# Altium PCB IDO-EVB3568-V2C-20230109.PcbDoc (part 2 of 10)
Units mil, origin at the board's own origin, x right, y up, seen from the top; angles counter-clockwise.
Board outline 5318 x 3544 mil, 2 copper layers (TOP, BOTTOM), stack 6.8 mil thick; 790 components, 626 nets, 2890 pads, 1922 vias.
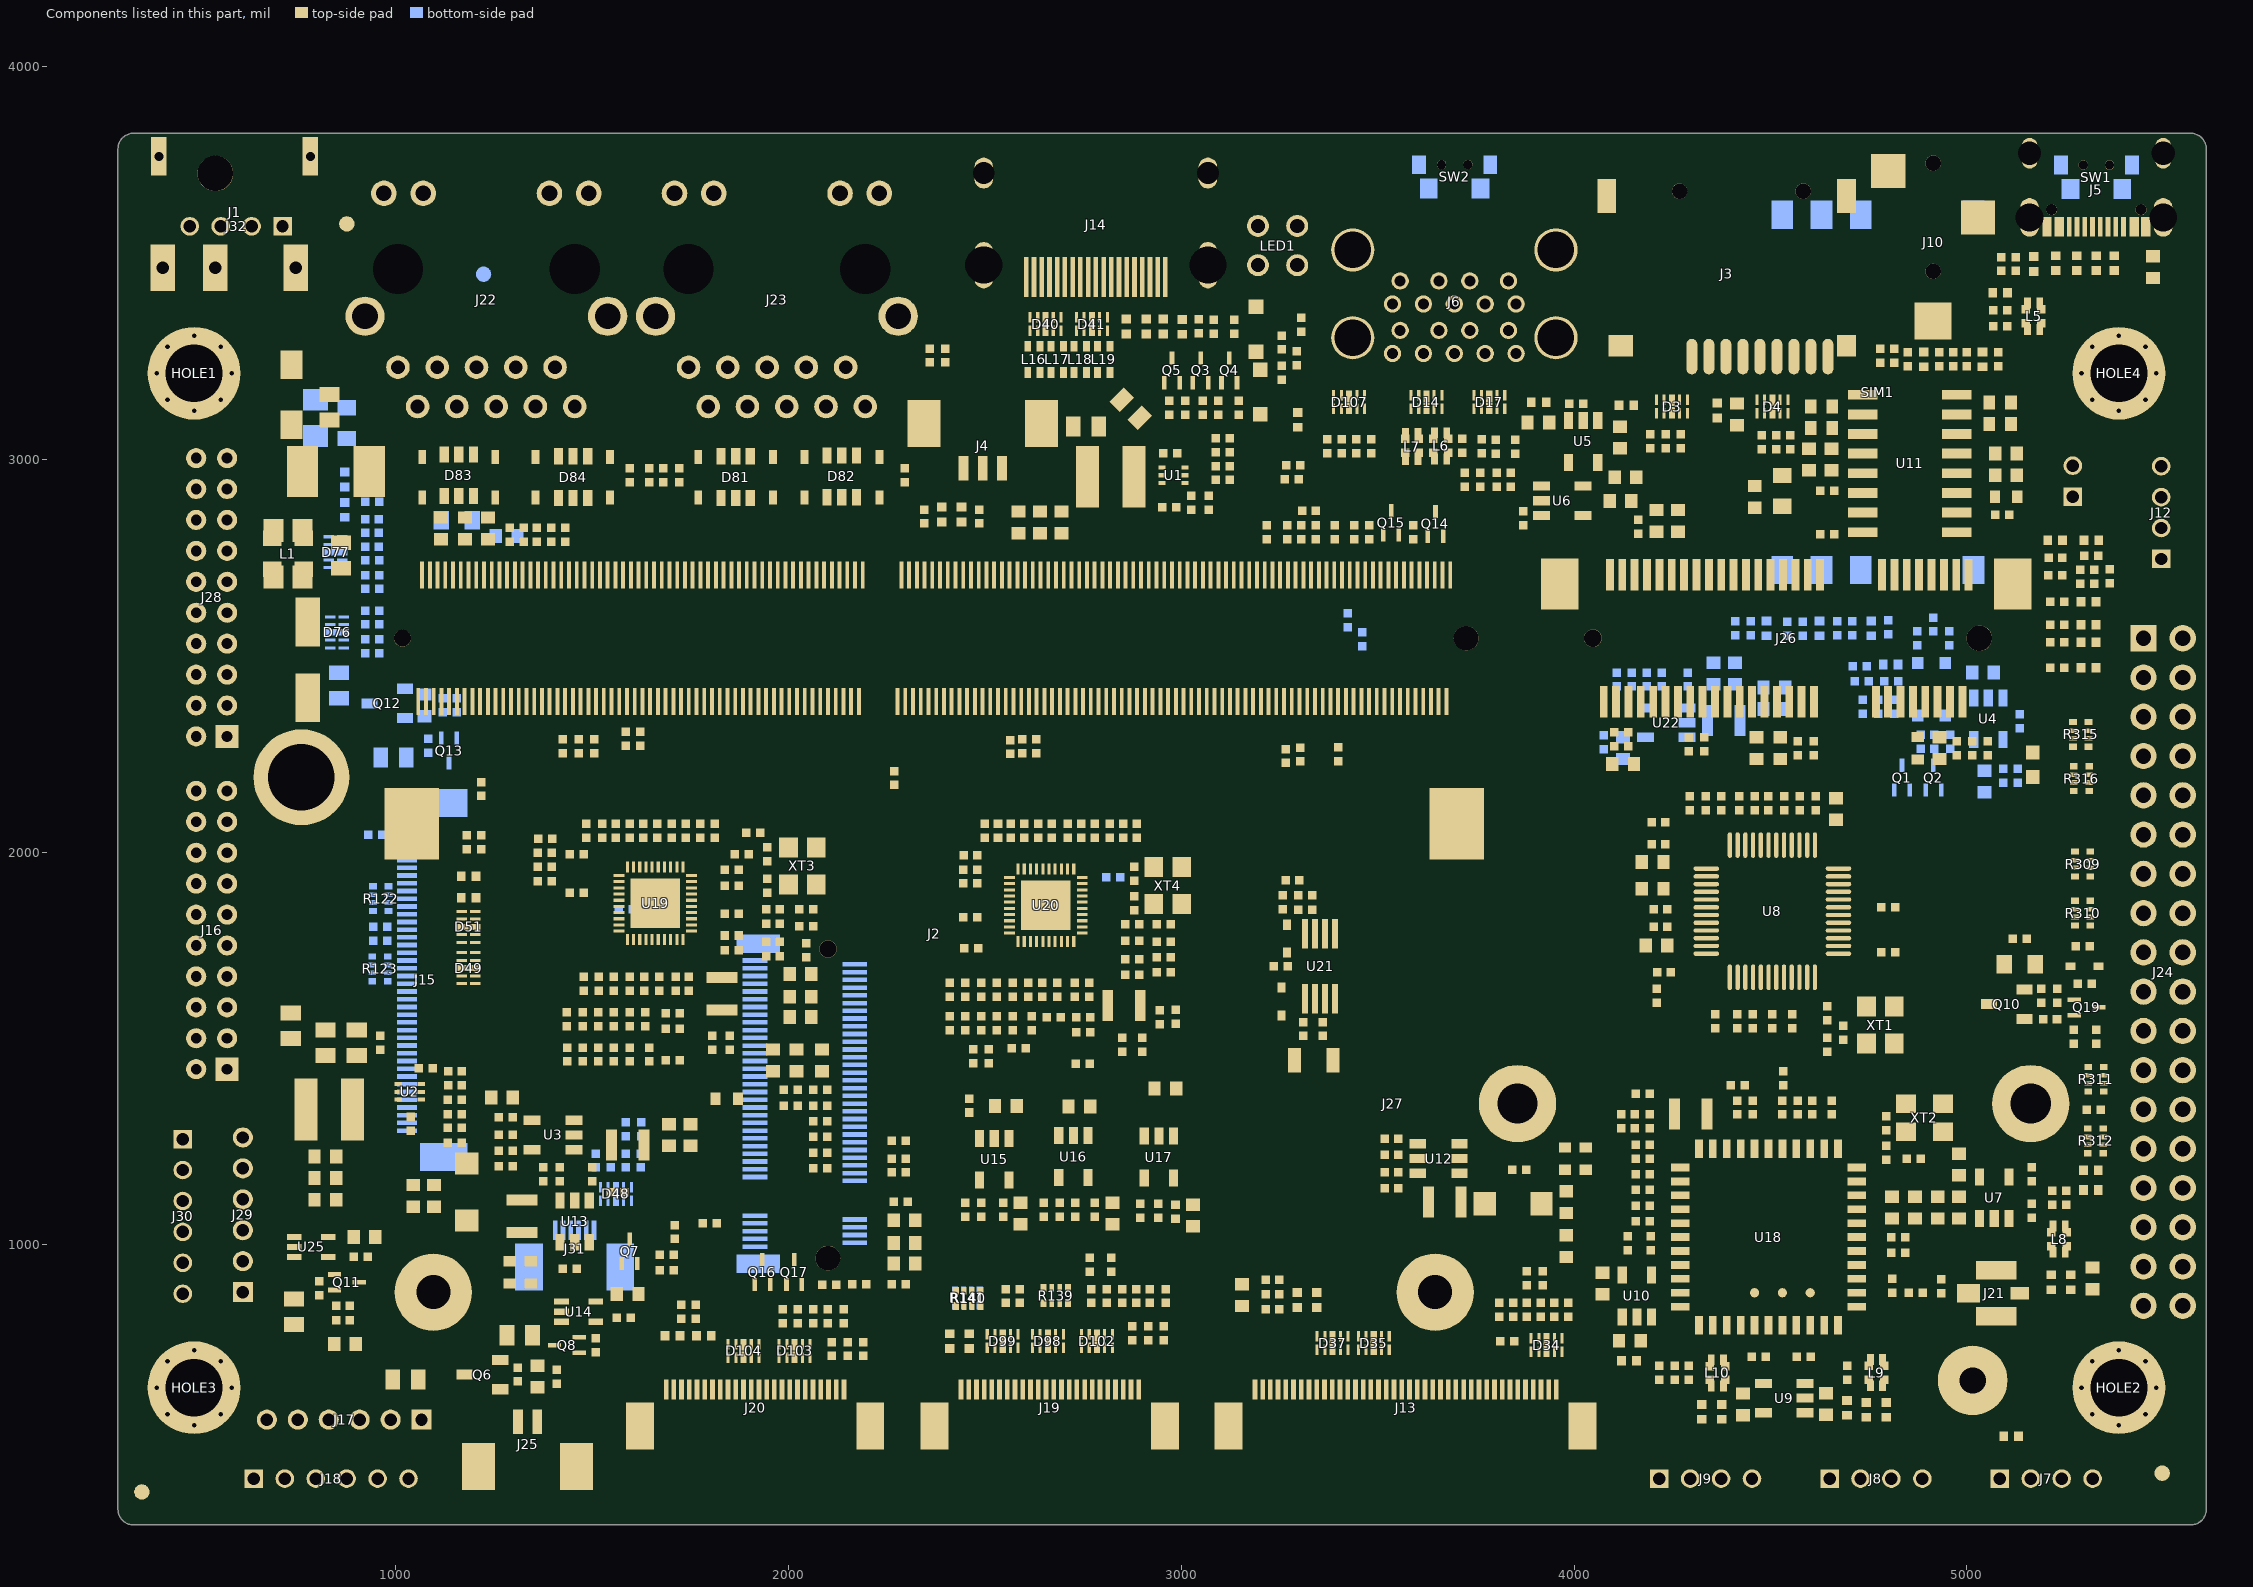
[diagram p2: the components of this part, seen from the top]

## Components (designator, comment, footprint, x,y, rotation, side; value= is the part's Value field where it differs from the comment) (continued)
R270 "R-0402_R0402_100R" SILKSCREEN_TOP#1 2875,1817 r180 top
R271 "R-0402_R0402_120R" SILKSCREEN_TOP#1 2955,1772 r180 top
R272 "R-0402_R0402_22R" SILKSCREEN_TOP#1 3269,2815 r90 top
R273 "R-0402_R0402_NC/4.7K" SILKSCREEN_TOP#1 2875,1688 r180 top
R274 "R-0402_R0402_4.7K" SILKSCREEN_TOP#1 2955,1695 r0 top
R275 "R-0402_R0402_22R" SILKSCREEN_TOP#1 3218,2815 r90 top
R276 "R-0402_R0402_22R" SILKSCREEN_TOP#1 3440,2815 r90 top
R277 "R-0402_R0402_NC/4.7K" SILKSCREEN_TOP#1 2875,1775 r180 top
R278 "R-0402_R0402_4.7K" SILKSCREEN_TOP#1 2955,1733 r0 top
R279 "R-0402_R0402_22R" SILKSCREEN_TOP#1 3390,2815 r90 top
R280 "R-0402_R0402_22R" SILKSCREEN_TOP#1 3400,2250 r270 top
R281 "R-0402_R0402_4.7K" SILKSCREEN_TOP#1 2875,1727 r180 top
R282 "R-0402_R0402_22R" SILKSCREEN_TOP#1 3342,2815 r90 top
R283 "R-0402_R0402_4.7K" SILKSCREEN_TOP#1 2410,1565 r270 top
R284 "R-0402_R0402_4.7K" SILKSCREEN_TOP#1 2646,1650 r90 top
R285 "R-0402_R0402_NC/4.7K" SILKSCREEN_TOP#1 2675,1580 r0 top
R286 "R-0402_R0402_4.7K" SILKSCREEN_TOP#1 2570,1650 r90 top
R287 "R-0402_R0402_4.7K" SILKSCREEN_TOP#1 2586,1501 r180 top
R288 "R-0402_R0402_NC/4.7K" SILKSCREEN_TOP#1 2530,1565 r270 top
R289 "R-0402_R0402_2.49K" SILKSCREEN_TOP#1 2886,2055 r270 top
R290 "R-0402_R0402_4.7K" SILKSCREEN_TOP#1 2490,1565 r90 top
R291 "R-0402_R0402_NC/4.7K" SILKSCREEN_TOP#1 2510,1480 r270 top
R293 "R-0402_R0402_NC/4.7K" SILKSCREEN_TOP#1 2450,1565 r90 top
R294 "R-0402_R0402_4.7K" SILKSCREEN_TOP#1 2470,1480 r270 top
R296 "R-0402_R0402_0R" SILKSCREEN_TOP#1 2462,1921 r0 top
R297 "R-0402_R0402_1.8K" SILKSCREEN_TOP#1 2462,1835 r180 top
R298 "R-0402_R0402_0R" SILKSCREEN_TOP#1 2749,1461 r180 top
R300 "R-0402_R0402_22R" SILKSCREEN_TOP#1 2530,1650 r270 top
R301 "R-0402_R0402_22R" SILKSCREEN_TOP#1 2490,1650 r270 top
R302 "R-0402_R0402_22R" SILKSCREEN_TOP#1 2450,1650 r270 top
R303 "R-0402_R0402_22R" SILKSCREEN_TOP#1 2410,1650 r270 top
R304 "R-0402_R0402_22R" SILKSCREEN_TOP#1 2610,1650 r270 top
R305 "R-0402_R0402_22R" SILKSCREEN_TOP#1 2570,1565 r270 top
R306 "R-0402_R0402_0R" SILKSCREEN_TOP#1 2986,1581 r90 top
R307 "R-0402_R0402_NC/2.2R" SILKSCREEN_TOP#1 5217,1120 r90 top
R308 "R-0402_R0402_NC/2.2R" SILKSCREEN_TOP#1 5253,1120 r90 top
R309 "RN_0402X4_RN_0402X4_22R" SILKSCREEN_TOP#28 5295,1970 r0 top
R310 "RN_0402X4_RN_0402X4_22R" SILKSCREEN_TOP#28 5295,1845 r0 top
R311 "RN_0402X4_RN_0402X4_22R" SILKSCREEN_TOP#28 5329,1422 r0 top
R312 "RN_0402X4_RN_0402X4_22R" SILKSCREEN_TOP#28 5328,1265 r0 top
R314 "R-0402_R0402_22R" SILKSCREEN_TOP#1 5323,1344 r0 top
R315 "RN_0402X4_RN_0402X4_22R" SILKSCREEN_TOP#28 5290,2300 r0 top
R316 "RN_0402X4_RN_0402X4_22R" SILKSCREEN_TOP#28 5292,2187.52 r0 top
R326 "R-0402_R0402_2.2K" SILKSCREEN_TOP#1 3283,1929 r180 top
R327 "R-0402_R0402_2.2K" SILKSCREEN_TOP#1 3258,1873 r90 top
R328 "R-0402_R0402_22R" SILKSCREEN_TOP#1 3315,1853 r180 top
R329 "R-0402_R0402_22R" SILKSCREEN_TOP#1 3315,1890 r180 top
R330 "R-0402_R0402_100R" ASSEMBLY_TOP#2 5085,3380 r0 top
R331 "R-0402_R0402_15K" ASSEMBLY_BOTTOM#3 4727,2474 r0 bottom
R332 "R-0402_R0402_10K" ASSEMBLY_BOTTOM#2 4543,2569 r270 bottom
R333 "R-0603_R0603_0R" ASSEMBLY_TOP#26 4875,2265 r270 top
R334 "R-0402_R0402_22R" ASSEMBLY_BOTTOM#3 4808,2436 r0 bottom
R335 "R-0402_R0402_22R" ASSEMBLY_BOTTOM#2 4800,2573 r270 bottom
R336 "R-0402_R0402_22R" ASSEMBLY_BOTTOM#2 4670,2570 r270 bottom
R337 "R-0402_R0402_22R" ASSEMBLY_TOP#2 4610,2265 r270 top
R340 "R-0402_R0402_0R" ASSEMBLY_TOP#2 4331,2275 r270 top
R341 "R-0402_R0402_0R" ASSEMBLY_TOP#2 4292,2275 r270 top
R342 "R-0402_R0402_1K" ASSEMBLY_TOP#2 5053,2265 r90 top
R343 "R-0402_R0402_53.6K" ASSEMBLY_BOTTOM#2 4185,2440 r90 bottom
R344 "R-0402_R0402_22R" ASSEMBLY_BOTTOM#2 4290,2440 r270 bottom
R345 "R-0402_R0402_10K" ASSEMBLY_BOTTOM#2 4109,2440 r270 bottom
R347 "R-0402_R0402_22R" SILKSCREEN_TOP#1 2280,1265 r180 top
R348 "R-0402_R0402_22R" SILKSCREEN_TOP#1 2280,1220 r180 top
R349 "R-0402_R0402_22R" SILKSCREEN_TOP#1 2280,1185 r180 top
R352 "R-0402_R0402_22R" SILKSCREEN_TOP#1 2285,1110 r180 top
R355 "R-0402_R0402_2.2R" SILKSCREEN_TOP#1 2080,1315 r180 top
R356 "R-0402_R0402_2.2R" SILKSCREEN_TOP#1 2080,1275 r180 top
R357 "R-0402_R0402_2.2R" SILKSCREEN_TOP#1 2005,1395 r180 top
R358 "R-0402_R0402_2.2R" SILKSCREEN_TOP#1 2005,1355 r180 top
R359 "R-0603_R0603_0R" SILKSCREEN_TOP#27 1842,1372 r0 top
R360 "R-0402_R0402_2.2R" SILKSCREEN_TOP#1 2080,1235 r180 top
R361 "R-0402_R0402_2.2R" SILKSCREEN_TOP#1 2080,1195 r180 top
R375 "R-0402_R0402_2.2R" SILKSCREEN_TOP#1 3715,3035 r90 top
R376 "R-0402_R0402_2.2R" SILKSCREEN_TOP#1 3765,3034 r90 top
R382 "R-0402_R0402_NC/22R" SILKSCREEN_TOP#1 1799,1055 r180 top
R384 "R-0402_R0402_NC/100K" SILKSCREEN_BOTTOM#3 940,2743 r0 bottom
R385 "R-0402_R0402_NC/100K" SILKSCREEN_BOTTOM#2 939,2848 r0 bottom
R387 "R-0402_R0402_NC/10K" SILKSCREEN_TOP#1 865,808 r0 top
R388 "R-0402_R0402_NC/10K" SILKSCREEN_TOP#1 805,890 r270 top
R389 "R-0402_R0402_0R" SILKSCREEN_TOP#1 865,845 r180 top
R390 "R-0402_R0402_0R" SILKSCREEN_TOP#1 910,970 r180 top
R391 "R-0402_R0402_100K" SILKSCREEN_BOTTOM#2 1119,2374 r270 bottom
R392 "R-0402_R0402_10K" SILKSCREEN_BOTTOM#2 1155,2374 r270 bottom
R393 "R-0402_R0402_1K" SILKSCREEN_BOTTOM#2 1082,2271 r270 bottom
R394 "R-0402_R0402_22R" SILKSCREEN_TOP#1 4825,980 r180 top
R398 "R-0402_R0402_10K" ASSEMBLY_TOP#2 5295,1760 r180 top
R399 "R-0402_R0402_10K" ASSEMBLY_TOP#2 5273,1530 r90 top
R400 "R-0402_R0402_10K" SILKSCREEN_TOP#1 5330,1530 r90 top
R401 "R-0402_R0402_10K" ASSEMBLY_TOP#2 5300,1665 r0 top
R408 "R-0402_R0402_NC/0R" SILKSCREEN_TOP#1 1168,1425 r90 top
R409 "R-0402_R0402_0R" SILKSCREEN_TOP#1 1133,1425 r90 top
R412 "R-0402_R0402_100R" SILKSCREEN_TOP#1 3285,2985 r0 top
R413 "R-0402_R0402_NC/0R" SILKSCREEN_TOP#1 3845,835 r270 top
R415 "R-0402_R0402_0R" SILKSCREEN_TOP#1 3810,835 r270 top
R416 "R-0402_R0402_22R" SILKSCREEN_TOP#1 2460,1355 r270 top
R417 "R-0402_R0402_22R" SILKSCREEN_TOP#1 1217,2025 r270 top
R418 "R-0402_R0402_22R" SILKSCREEN_TOP#1 3232,912 r0 top
R419 "R-0805_R0805_1M" SILKSCREEN_BOTTOM#15 875,3093 r90 bottom
R421 "R-0402_R0402_120R" SILKSCREEN_TOP#1 2595,2270 r270 top
R422 "R-0402_R0402_NC/0R" SILKSCREEN_TOP#1 3761,2949 r270 top
R423 "R-0402_R0402_NC/0R" SILKSCREEN_TOP#1 3722,2949 r270 top
R424 "R-0402_R0402_2.2R" SILKSCREEN_TOP#1 1595,2055 r90 top
R425 "R-0402_R0402_2.2R" SILKSCREEN_TOP#1 1630,2055 r90 top
SIM1 "J-SIM-021_0_SIM-91288-021_SIM" SILKSCREEN_BOTTOM#18 4613.43,3238.46 r270 bottom
SW1 "SW-TS24CA_PB-SIDE-S-3_5X4_5_T-S" SILKSCREEN_BOTTOM#19 5328.5,3720.5 r0 bottom
SW2 "SW-TS24CA_PB-SIDE-S-3_5X4_5_T-S" SILKSCREEN_BOTTOM#19 3694.5,3721.5 r0 bottom
U1 "U-ETA1654FSG_SOT563_ETA1654FSG" SILKSCREEN_TOP#29 2980,2960 r0 top
U2 "U-ETA1654FSG_SOT563_ETA1654FSG" SILKSCREEN_TOP#29 1035,1390 r0 top
U3 "U-ETA3417S2F_SOT23-5_ETA3417S2F" SILKSCREEN_TOP#30 1400,1280 r180 top
U4 "U-SY6280AAC_1_SOT23-5_SY6280AAC" SILKSCREEN_BOTTOM#20 5055,2340 r270 bottom
U5 "U-SY6280AAC_1_SOT23-5_SY6280AAC" SILKSCREEN_TOP#30 4023,3046 r270 top
U6 "U-SY6280AAC_1_SOT23-5_SY6280AAC" SILKSCREEN_TOP#30 3970,2895 r0 top
U7 "U-SY6280AAC_1_SOT23-5_SY6280AAC" SILKSCREEN_TOP#30 5070,1120 r90 top
U8 "U-FE2_0.1_LQFP-48_7X7X05P_FE1.1" ASSEMBLY_TOP#28 4505,1850 r90 top
U9 "U-SY6280AAC_1_SOT23-5_SY6280AAC" SILKSCREEN_TOP#30 4535,610 r180 top
U10 "U-SY6280AAC_1_SOT23-5_SY6280AAC" SILKSCREEN_TOP#30 4160,870 r90 top
U11 "U-NS4205_SOP16-P127-390X990_NS4" ASSEMBLY_TOP#29 4855,2990 r0 top
U12 "U-SY7201A_2_SOT23-6_SY7201ABC" SILKSCREEN_TOP#12 3655,1220 r180 top
U13 "U-SY7201A_2_SOT23-6_SY7201ABC" SILKSCREEN_TOP#12 1455,1060 r90 top
U14 "U-74LVC1G125GW-125_SOT353_NC/74" SILKSCREEN_TOP#31 1465,830 r0 top
U15 "U-ETA5050_SOT23-5_ETA5050V0S2F" SILKSCREEN_TOP#30 2523.57,1218.22 r270 top
U16 "U-ETA5050_SOT23-5_ETA5050V0S2F" SILKSCREEN_TOP#30 2725,1225 r270 top
U17 "U-ETA5050_SOT23-5_ETA5050V0S2F" SILKSCREEN_TOP#30 2942.72,1223.93 r270 top
U18 "MODULE_AP6XXX_WIFI_44P_12X12_AP" ASSEMBLY_TOP#30 4495,1020 r180 top
U19 "ETHERNET_RTL8211F_QFN-40_5X5X04" SILKSCREEN_TOP#32 1660,1870 r270 top
U20 "ETHERNET_RTL8211F_QFN-40_5X5X04" SILKSCREEN_TOP#32 2655,1865 r270 top
U21 "U-HYM8563S_TSSOP-8_HYM8563S" INFORMATION 3353,1710 r90 top
U22 "U-ETA3417_1_SOT23-5_ETA3417" SILKSCREEN_BOTTOM#21 4235,2330 r0 bottom
U25 "U-74LVC1G125GW-125_SOT353_NC/74" SILKSCREEN_TOP#31 783.84,995 r0 top
XT1 "XTAL-4P_XTAL_32X25_4P_IC_12MHZ" SILKSCREEN_TOP#33 4780,1560 r0 top
XT2 "XTAL-4P_XTAL_32X25_4P_IC_NC/26M" SILKSCREEN_TOP#33 4892,1324 r90 top
XT3 "XTAL-4P_XTAL_32X25_4P_IC_25MHZ" SILKSCREEN_TOP#33 2035,1965 r0 top
XT4 "XTAL-4P_XTAL_32X25_4P_IC_25MHZ" SILKSCREEN_TOP#33 2965,1915 r0 top
XT5 "XTAL-2P_XTAL_32X15_2P_IC_32.768" SILKSCREEN_TOP#34 3337,1470 r180 top

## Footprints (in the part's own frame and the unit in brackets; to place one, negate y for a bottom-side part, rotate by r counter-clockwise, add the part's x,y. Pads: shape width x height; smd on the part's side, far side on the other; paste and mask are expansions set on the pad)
ASSEMBLY_BOTTOM#1 [mm] "ASSEMBLY_BOTTOM"
  rect 0.8x0.9 smd: 1(-0.7,0) 2(0.7,0)
  silkscreen extent -1.35,-0.6 1.35,0.6, body extent -1.35,-0.6 1.35,0.6, height 3.81
ASSEMBLY_BOTTOM#2 [mm] "ASSEMBLY_BOTTOM"
  rect 0.55x0.55 smd: 1(-0.45,0) 2(0.45,0)
  TOP keep-out region: -0.127,-0.381 -0.127,0.381 0.127,0.381 0.127,-0.381
  silkscreen extent -0.9,-0.4 0.9,0.4, body extent -0.9,-0.4 0.9,0.4, height 3.81
ASSEMBLY_BOTTOM#3 [mm] "ASSEMBLY_BOTTOM"
  rect 0.55x0.55 smd: 1(0.45,0) 2(-0.45,0)
  TOP keep-out region: 0.127,0.381 0.127,-0.381 -0.127,-0.381 -0.127,0.381 0.127,0.381
  silkscreen extent -0.9,-0.4 0.9,0.4, body extent -0.9,-0.4 0.9,0.4, height 3.81
ASSEMBLY_BOTTOM#4 [mm] "ASSEMBLY_BOTTOM"
  rect 0.8x0.9 smd: 1(0.7,0) 2(-0.7,0)
  silkscreen extent -1.35,-0.6 1.35,0.6, body extent -1.35,-0.6 1.35,0.6, height 3.81
ASSEMBLY_BOTTOM#5 [mm] "ASSEMBLY_BOTTOM"
  round 6 / inner round 1.524 / far side round 6 hole 3.7: 1(0,0)
  round 0 / inner round 1.524 / far side round 0 hole 0.3: ""(-2.425,0)
  round 0.95 / inner round 1.524 / far side round 0.95 hole 0.3: ""(-1.715,-1.715) ""(-1.715,1.715) ""(0,-2.425) ""(0,2.425) ""(1.715,-1.715) ""(1.715,1.715) ""(2.425,0)
  body extent -3.01,-3.01 3.01,3.01, height 3.81
ASSEMBLY_BOTTOM#6 [mm] "ASSEMBLY_BOTTOM"
  rect 0.305x1.27 smd: 1(9.75,2.925) 2(9.25,2.925) 3(8.75,2.925) 4(8.25,2.925) 5(7.75,2.925) 6(7.25,2.925) 7(6.75,2.925) 8(6.25,2.925) 9(5.75,2.925) 10(5.25,2.925) 11(4.75,2.925) 12(4.25,2.925) 13(3.75,2.925) 14(3.25,2.925) 15(2.75,2.925) 16(2.25,2.925) 17(1.75,2.925) 18(1.25,2.925) 19(0.75,2.925) 20(0.25,2.925) 21(-0.25,2.925) 22(-0.75,2.925) 23(-1.25,2.925) 24(-1.75,2.925) 25(-2.25,2.925) 26(-2.75,2.925) 27(-3.25,2.925) 28(-3.75,2.925) 29(-4.25,2.925) 30(-4.75,2.925) 31(-5.25,2.925) 32(-5.75,2.925) 33(-6.25,2.925) 34(-6.75,2.925) 35(-7.25,2.925) 36(-7.75,2.925) 37(-8.25,2.925) 38(-8.75,2.925) 39(-9.25,2.925) 40(-9.75,2.925)
  rect 1.803x3.048 smd: 41(11.45,0.55) 42(-11.45,0.55)
  silkscreen extent -12.5,-3.65 12.5,3.54, body extent -12.5,-3.65 12.5,3.65, height 3.81
ASSEMBLY_BOTTOM#7 [mm] "ASSEMBLY_BOTTOM"
  rect 0.305x1.27 smd: 1(-1.25,-2.925) 2(-0.75,-2.925) 3(-0.25,-2.925) 4(0.25,-2.925) 5(0.75,-2.925) 6(1.25,-2.925)
  rect 1.803x3.048 smd: 7(-2.95,-0.55) 8(2.95,-0.55)
  silkscreen extent -4,-4.35 4,3.65, body extent -4,-3.65 4,3.65, height 3.81
ASSEMBLY_BOTTOM#8 [mm] "ASSEMBLY_BOTTOM"
  rect 0.7x2 smd: 1(-1.037,0) 2(1.063,0)
  TOP keep-out region: -0.597,-1.016 -0.597,1.016 0.622,1.016 0.622,-1.016 -0.597,-1.016
  silkscreen extent -1.51,-1.14 1.54,1.14, body extent -1.46,-1.04 1.46,1.04, height 3.81
ASSEMBLY_TOP#1 [mm] "ASSEMBLY_TOP"
  rect 0.8x0.9 smd: 1(-0.7,0) 2(0.7,0)
  silkscreen extent -1.35,-0.6 1.35,0.6, body extent -1.35,-0.6 1.35,0.6, height 3.81
ASSEMBLY_TOP#2 [mm] "ASSEMBLY_TOP"
  rect 0.55x0.55 smd: 1(-0.45,0) 2(0.45,0)
  TOP keep-out region: -0.127,-0.381 0.127,-0.381 0.127,0.381 -0.127,0.381 -0.127,-0.381
  silkscreen extent -0.9,-0.4 0.9,0.4, body extent -0.9,-0.4 0.9,0.4, height 3.81
ASSEMBLY_TOP#3 [mm] "ASSEMBLY_TOP"
  rect 0.2x0.68 smd: 1(-1,-0.437) 2(-0.5,-0.437) 4(0.5,-0.437) 5(1,-0.437) 6(1,0.437) 7(0.5,0.437) 9(-0.5,0.437) 10(-1,0.437)
  rect 0.4x0.75 smd: 3(0,-0.395) 8(0,0.395)
  silkscreen extent -1.43,-0.5 1.25,1.69
ASSEMBLY_TOP#4 [mm] "ASSEMBLY_TOP"
  rect 2.032x3.302 smd: 1(-2.159,0) 2(2.159,0)
  TOP keep-out region: -1.6,1.699 -1.6,-1.699 1.6,-1.699 1.6,1.699 -1.6,1.699
  silkscreen extent -3.5,-1.9 3.5,1.9, body extent -2.35,-1.7 2.35,1.7, height 3.81
ASSEMBLY_TOP#5 [mm] "ASSEMBLY_TOP"
  round 6.2 / inner round 1.524 / far side round 5 hole 4.3: 1(0,0)
  body extent -3.11,-3.11 3.11,3.11, height 3.81
ASSEMBLY_TOP#6 [mm] "ASSEMBLY_TOP"
  round 6 / inner round 1.524 / far side round 6 hole 3.7: 1(0,0)
  round 0.95 / inner round 1.524 / far side round 0.95 hole 0.3: ""(-2.425,0) ""(-1.715,-1.715) ""(-1.715,1.715) ""(0,-2.425) ""(0,2.425) ""(1.715,-1.715) ""(1.715,1.715)
  round 0 / inner round 1.524 / far side round 0 hole 0.3: ""(2.425,0)
  body extent -3.01,-3.01 3.01,3.01, height 3.81
ASSEMBLY_TOP#7 [mm] "ASSEMBLY_TOP"
  rect 1.2x1.2 / inner round 1.524 / far side rect 1.2x1.2 hole 0.8: 1(3,-0.45)
  round 1.2 / inner round 1.524 / far side round 1.2 hole 0.8: 2(1,-0.45) 3(-1,-0.45) 4(-3,-0.45)
  silkscreen extent -5,-2.25 5,2.25, body extent -5,-2.25 5,2.25, height 3.81
ASSEMBLY_TOP#8 [mm] "ASSEMBLY_TOP"
  rect 2.2x2.2 smd: 1(-3.2,-2.9) 2(-0.2,2.901)
  rect 2.4x2.4 smd: 3(6.5,0.001)
  round 1 / inner round 1.524 / far side round 1 hole 1: ""(-3.7,0.001) ""(3.3,0.001)
  silkscreen extent -7.7,-2.9 6.5,2.7, body extent -7.7,-4 7.7,4, height 3.81
ASSEMBLY_TOP#9 [mm] "ASSEMBLY_TOP"
  rect 1.2x1.2 / inner round 1.524 / far side rect 1.2x1.2 hole 0.8: 1(1,-0.45)
  round 1.2 / inner round 1.524 / far side round 1.2 hole 0.8: 2(-1,-0.45)
  silkscreen extent -3,-2.25 3,2.25, body extent -3,-2.25 3,2.25, height 3.81
ASSEMBLY_TOP#10 [mm] "ASSEMBLY_TOP"
  rect 0.305x1.27 smd: 1(9.75,2.925) 2(9.25,2.925) 3(8.75,2.925) 4(8.25,2.925) 5(7.75,2.925) 6(7.25,2.925) 7(6.75,2.925) 8(6.25,2.925) 9(5.75,2.925) 10(5.25,2.925) 11(4.75,2.925) 12(4.25,2.925) 13(3.75,2.925) 14(3.25,2.925) 15(2.75,2.925) 16(2.25,2.925) 17(1.75,2.925) 18(1.25,2.925) 19(0.75,2.925) 20(0.25,2.925) 21(-0.25,2.925) 22(-0.75,2.925) 23(-1.25,2.925) 24(-1.75,2.925) 25(-2.25,2.925) 26(-2.75,2.925) 27(-3.25,2.925) 28(-3.75,2.925) 29(-4.25,2.925) 30(-4.75,2.925) 31(-5.25,2.925) 32(-5.75,2.925) 33(-6.25,2.925) 34(-6.75,2.925) 35(-7.25,2.925) 36(-7.75,2.925) 37(-8.25,2.925) 38(-8.75,2.925) 39(-9.25,2.925) 40(-9.75,2.925)
  rect 1.803x3.048 smd: 41(11.45,0.55) 42(-11.45,0.55)
  silkscreen extent -12.5,-3.65 12.5,4.35, body extent -12.5,-3.65 12.5,3.65, height 3.81
ASSEMBLY_TOP#11 [mm] "ASSEMBLY_TOP"
  rect 0.3x2.6 smd: 1(-4.5,-4.95) 2(-4,-4.95) 3(-3.5,-4.95) 4(-3,-4.95) 5(-2.5,-4.95) 6(-2,-4.95) 7(-1.5,-4.95) 8(-1,-4.95) 9(-0.5,-4.95) 10(0,-4.95) 11(0.5,-4.95) 12(1,-4.95) 13(1.5,-4.95) 14(2,-4.95) 15(2.5,-4.95) 16(3,-4.95) 17(3.5,-4.95) 18(4,-4.95) 19(4.5,-4.95)
  oval 1.2x3 / inner round 1.524 / far side oval 1.2x3 hole 2.4 slot 0.7 at 0 deg: 20(7.25,-4.19) 21(-7.25,-4.19)
  oval 1.2x2 / inner round 1.524 / far side oval 1.2x2 hole 1.4 slot 0.7 at 0 deg: 22(-7.25,1.77) 23(7.25,1.77)
  silkscreen extent -7.5,-7.16 7.5,6.45, body extent -7.5,-6.45 7.5,6.45, height 3.81
ASSEMBLY_TOP#12 [mm] "ASSEMBLY_TOP"
  rect 1.5x1.5 / inner round 1.524 / far side rect 1.5x1.5 hole 0.7: 1(-9,-1)
  round 1.3 / inner round 1.524 / far side round 1.3 hole 0.7: 2(-9,1) 3(-7,-1) 4(-7,1) 5(-5,-1) 6(-5,1) 7(-3,-1) 8(-3,1) 9(-1,-1) 10(-1,1) 11(1,-1) 12(1,1) 13(3,-1) 14(3,1) 15(5,-1) 16(5,1) 17(7,-1) 18(7,1) 19(9,-1) 20(9,1)
  silkscreen extent -10,-3 10,8.15, body extent -10,-2 10,2, height 3.81
ASSEMBLY_TOP#13 [mm] "ASSEMBLY_TOP"
  rect 1.3x1.3 / inner round 1.524 / far side rect 1.3x1.3 hole 0.8: 1(-5,0)
  round 1.3 / inner round 1.524 / far side round 1.3 hole 0.8: 2(-3,0) 3(-1,0) 4(1,0) 5(3,0) 6(5,0)
  silkscreen extent -6.9,-1.73 6,1, body extent -6,-1 6,1, height 3.81
ASSEMBLY_TOP#14 [mm] "ASSEMBLY_TOP"
  rect 1.2x1.2 / inner round 1.524 / far side rect 1.2x1.2 hole 0.8: 1(5,-0.45)
  round 1.2 / inner round 1.524 / far side round 1.2 hole 0.8: 2(3,-0.45) 3(1,-0.45) 4(-1,-0.45) 5(-3,-0.45) 6(-5,-0.45)
  silkscreen extent -7,-2.25 7,2.25, body extent -7,-2.25 7,2.25, height 3.81
ASSEMBLY_TOP#15 [mm] "ASSEMBLY_TOP"
  rect 0.305x1.27 smd: 1(5.75,2.925) 2(5.25,2.925) 3(4.75,2.925) 4(4.25,2.925) 5(3.75,2.925) 6(3.25,2.925) 7(2.75,2.925) 8(2.25,2.925) 9(1.75,2.925) 10(1.25,2.925) 11(0.75,2.925) 12(0.25,2.925) 13(-0.25,2.925) 14(-0.75,2.925) 15(-1.25,2.925) 16(-1.75,2.925) 17(-2.25,2.925) 18(-2.75,2.925) 19(-3.25,2.925) 20(-3.75,2.925) 21(-4.25,2.925) 22(-4.75,2.925) 23(-5.25,2.925) 24(-5.75,2.925)
  rect 1.803x3.048 smd: 25(7.45,0.55) 26(-7.45,0.55)
  silkscreen extent -8.5,-3.65 8.5,4.35, body extent -8.5,-3.65 8.5,3.65, height 3.81
ASSEMBLY_TOP#16 [mm] "ASSEMBLY_TOP"
  rect 1.2x0.8 smd: 1(-1.737,0)
  rect 1.5x1.2 smd: 2(1.587,0)
  rect 2.65x1.2 smd: 3(-0.212,-1.5) 4(-0.212,1.5)
  TOP keep-out region: 1.312,0.9 -1.112,0.9 -1.112,-0.9 1.312,-0.9 1.312,0.9
  silkscreen extent -1.91,-1.62 1.75,1.62, body extent -2.34,-2.1 2.34,2.1, height 3.81
ASSEMBLY_TOP#17 [mm] "ASSEMBLY_TOP"
  round 1.524 hole 0.889: 1(5.715,-9.14) 2(4.445,-6.6) 3(3.175,-9.14) 4(1.905,-6.6) 5(0.635,-9.14) 6(-0.635,-6.6) 7(-1.905,-9.14) 8(-3.175,-6.6) 9(-4.445,-9.14) 10(-5.715,-6.6)
  round 1.651 / inner round 1.524 / far side round 1.651 hole 1.016: 11(6.624,4.65) 12(4.084,4.65) 13(-4.084,4.65) 14(-6.624,4.65)
  round 2.54 / inner round 1.524 / far side round 2.54 hole 1.651: SH1(-7.846,-3.301) SH2(7.846,-3.301)
  round 2.997 / inner round 1.524 / far side round 2.997 hole 3.251 unplated: ""(-5.715,-0.25) ""(5.715,-0.25)
  Multi-Layer keep-out region: -3.495,-0.249 -3.537,0.184 -3.664,0.6 -3.869,0.984 -4.145,1.321 -4.481,1.597 -4.865,1.802 -5.282,1.928 -5.715,1.971 -6.148,1.928 -6.565,1.802 -6.82,1.665 -6.82,1.665 -6.949,1.597 -7.285,1.321 -7.561,0.984 -7.766,0.6 -7.893,0.184 -7.935,-0.249 -7.893,-0.683 -7.766,-1.099 -7.561,-1.483 -7.285,-1.82 -6.949,-2.096 -6.82,-2.164 -6.82,-2.164 -6.565,-2.301 -6.148,-2.427 -5.715,-2.47 -5.282,-2.427 -4.865,-2.301 -4.481,-2.096 -4.145,-1.82 -3.869,-1.483 -3.664,-1.099 -3.537,-0.683 -3.495,-0.249
  Multi-Layer keep-out region: 7.935,-0.249 7.893,0.184 7.766,0.6 7.561,0.984 7.285,1.321 6.949,1.597 6.565,1.802 6.148,1.928 5.715,1.971 5.282,1.928 4.865,1.802 4.61,1.665 4.61,1.665 4.481,1.597 4.145,1.321 3.869,0.984 3.664,0.6 3.537,0.184 3.495,-0.249 3.537,-0.683 3.664,-1.099 3.869,-1.483 4.145,-1.82 4.481,-2.096 4.61,-2.164 4.61,-2.164 4.865,-2.301 5.282,-2.427 5.715,-2.47 6.148,-2.427 6.565,-2.301 6.949,-2.096 7.285,-1.82 7.561,-1.483 7.766,-1.099 7.893,-0.683 7.935,-0.249
  silkscreen extent -8.1,-10.65 8.1,10.65, body extent -8.1,-10.65 8.1,10.65, height 3.81
ASSEMBLY_TOP#18 [mm] "ASSEMBLY_TOP"
  rect 1.7x1.7 / inner round 1.524 / far side rect 1.7x1.7 hole 1: 1(-21.59,-1.27)
  round 1.7 / inner round 1.524 / far side round 1.7 hole 1: 2(-21.59,1.27) 3(-19.05,-1.27) 4(-19.05,1.27) 5(-16.51,-1.27) 6(-16.51,1.27) 7(-13.97,-1.27) 8(-13.97,1.27) 9(-11.43,-1.27) 10(-11.43,1.27) 11(-8.89,-1.27) 12(-8.89,1.27) 13(-6.35,-1.27) 14(-6.35,1.27) 15(-3.81,-1.27) 16(-3.81,1.27) 17(-1.27,-1.27) 18(-1.27,1.27) 19(1.27,-1.27) 20(1.27,1.27) 21(3.81,-1.27) 22(3.81,1.27) 23(6.35,-1.27) 24(6.35,1.27) 25(8.89,-1.27) 26(8.89,1.27) 27(11.43,-1.27) 28(11.43,1.27) 29(13.97,-1.27) 30(13.97,1.27) 31(16.51,-1.27) 32(16.51,1.27) 33(19.05,-1.27) 34(19.05,1.27) 35(21.59,-1.27) 36(21.59,1.27)
  silkscreen extent -22.86,-3.54 22.86,2.54, body extent -22.86,-2.54 22.86,2.54, height 3.81
ASSEMBLY_TOP#19 [mm] "ASSEMBLY_TOP"
  rect 1.2x1.2 / inner round 1.524 / far side rect 1.2x1.2 hole 0.8: 1(5,-2.45)
  round 1.2 / inner round 1.524 / far side round 1.2 hole 0.8: 2(3,-2.45) 3(1,-2.45) 4(-1,-2.45) 5(-3,-2.45) 6(-5,-2.45)
  silkscreen extent -7,-3.8 7,3.8, body extent -7,-3.8 7,3.8, height 3.81
ASSEMBLY_TOP#20 [mm] "ASSEMBLY_TOP"
  rect 1.5x1.3 smd: 1(-1.5,0.95) 2(-1.5,-0.95) 3(1.5,-0.95) 4(1.5,0.95)
  silkscreen extent -2.3,-1.7 2.3,1.7, body extent -2.3,-1.7 2.3,1.7, height 3.81
ASSEMBLY_TOP#21 [mm] "ASSEMBLY_TOP"
  rect 1.5x4 smd: 1(-1.5,0) 2(1.5,0)
  TOP keep-out region: -0.676,-2.013 0.683,-2.013 0.683,2.02 -0.676,2.02 -0.676,-2.013
  silkscreen extent -2.41,-2.16 2.41,2.16, body extent -2.29,-2.03 2.29,2.03, height 3.81
ASSEMBLY_TOP#22 [mm] "ASSEMBLY_TOP"
  rect 0.7x2 smd: 1(-1.037,0) 2(1.063,0)
  TOP keep-out region: -0.597,-1.016 0.622,-1.016 0.622,1.016 -0.597,1.016
  silkscreen extent -1.51,-1.14 1.54,1.14, body extent -1.46,-1.04 1.46,1.04, height 3.81
ASSEMBLY_TOP#23 [mm] "ASSEMBLY_TOP"
  round 1.422 / inner round 1.524 / far side round 1.422 hole 0.914: 1(-1.27,1.83) 2(1.27,1.83) 3(-1.27,4.37) 4(1.27,4.37)
  silkscreen extent -3.1,-5.75 2.15,5.75, body extent -2.15,-5.75 2.15,5.75, height 3.81
ASSEMBLY_TOP#24 [mm] "ASSEMBLY_TOP"
  rect 0.9x0.9 smd: 1(-0.8,0) 2(0.8,0)
  silkscreen extent -2.16,-0.65 1.4,0.65, body extent -1.25,-0.45 1.25,0.45, height 3.81
ASSEMBLY_TOP#25 [mm] "ASSEMBLY_TOP"
  round 1 smd: 1(0,0)
  TOP keep-out region: 1.261,0 1.218,0.326 1.092,0.63 0.892,0.892 0.63,1.092 0.326,1.218 0,1.261 -0.326,1.218 -0.63,1.092 -0.63,1.092 -0.892,0.892 -1.092,0.63 -1.218,0.326 -1.261,0 -1.218,-0.326 -1.092,-0.63 -0.892,-0.892 -0.63,-1.092 -0.63,-1.092 -0.326,-1.218 0,-1.261 0.326,-1.218 0.63,-1.092 0.892,-0.892 1.092,-0.63 1.218,-0.326 1.261,0
  TOP keep-out region: 1.261,0 1.218,0.326 1.092,0.63 0.892,0.892 0.63,1.092 0.326,1.218 0,1.261 -0.326,1.218 -0.63,1.092 -0.63,1.092 -0.892,0.892 -1.092,0.63 -1.218,0.326 -1.261,0 -1.218,-0.326 -1.092,-0.63 -0.892,-0.892 -0.63,-1.092 -0.63,-1.092 -0.326,-1.218 0,-1.261 0.326,-1.218 0.63,-1.092 0.892,-0.892 1.092,-0.63 1.218,-0.326 1.261,0
  body extent -1.26,-1.26 1.26,1.26, height 3.81
ASSEMBLY_TOP#26 [mm] "ASSEMBLY_TOP"
  rect 0.65x0.8 smd: 1(-0.725,0) 2(0.725,0)
  TOP keep-out region: -0.254,0.381 -0.254,-0.381 0.254,-0.381 0.254,0.381 -0.254,0.381
  silkscreen extent -1.35,-0.6 1.35,0.6, body extent -1.4,-0.64 1.4,0.64, height 3.81
ASSEMBLY_TOP#27 [mm] "ASSEMBLY_TOP"
  rect 1x1.2 smd: 1(-1,0) 2(1,0)
  TOP keep-out region: -0.381,0.635 -0.381,-0.635 0.381,-0.635 0.381,0.635 -0.381,0.635
  silkscreen extent -1.7,-0.95 1.7,0.95, body extent -1.78,-1.02 1.78,1.02, height 3.81
ASSEMBLY_TOP#28 [mm] "ASSEMBLY_TOP"
  oval 1.651x0.279 smd: 1(-4.275,2.751) 2(-4.275,2.25) 3(-4.275,1.75) 4(-4.275,1.25) 5(-4.275,0.749) 6(-4.275,0.249) 7(-4.275,-0.249) 8(-4.275,-0.749) 9(-4.275,-1.25) 10(-4.275,-1.75) 11(-4.275,-2.25) 12(-4.275,-2.751) 25(4.275,-2.751) 26(4.275,-2.25) 27(4.275,-1.75) 28(4.275,-1.25) 29(4.275,-0.749) 30(4.275,-0.249) 31(4.275,0.249) 32(4.275,0.749) 33(4.275,1.25) 34(4.275,1.75) 35(4.275,2.25) 36(4.275,2.751)
  oval 0.279x1.651 smd: 13(-2.751,-4.275) 14(-2.25,-4.275) 15(-1.75,-4.275) 16(-1.25,-4.275) 17(-0.749,-4.275) 18(-0.249,-4.275) 19(0.249,-4.275) 20(0.749,-4.275) 21(1.25,-4.275) 22(1.75,-4.275) 23(2.25,-4.275) 24(2.751,-4.275) 37(2.751,4.275) 38(2.25,4.275) 39(1.75,4.275) 40(1.25,4.275) 41(0.749,4.275) 42(0.249,4.275) 43(-0.249,4.275) 44(-0.749,4.275) 45(-1.25,4.275) 46(-1.75,4.275) 47(-2.25,4.275) 48(-2.751,4.275)
  silkscreen extent -6.5,-6.5 6.5,6.5, body extent -4.5,-4.5 4.5,4.5, height 3.81
ASSEMBLY_TOP#29 [mm] "ASSEMBLY_TOP"
  rect 1.905x0.635 smd: 1(-3.048,4.445) 2(-3.048,3.175) 3(-3.048,1.905) 4(-3.048,0.635) 5(-3.048,-0.635) 6(-3.048,-1.905) 7(-3.048,-3.175) 8(-3.048,-4.445) 9(3.048,-4.445) 10(3.048,-3.175) 11(3.048,-1.905) 12(3.048,-0.635) 13(3.048,0.635) 14(3.048,1.905) 15(3.048,3.175) 16(3.048,4.445)
  silkscreen extent -5.09,-4.95 1.91,4.95
ASSEMBLY_TOP#30 [mm] "ASSEMBLY_TOP"
  rect 1.2x0.5 smd: 1(-5.7,4.5) 2(-5.7,3.6) 3(-5.7,2.7) 4(-5.7,1.8) 5(-5.7,0.9) 6(-5.7,0) 7(-5.7,-0.9) 8(-5.7,-1.8) 9(-5.7,-2.7) 10(-5.7,-3.6) 11(-5.7,-4.5) 23(5.7,-4.5) 24(5.7,-3.6) 25(5.7,-2.7) 26(5.7,-1.8) 27(5.7,-0.9) 28(5.7,0) 29(5.7,0.9) 30(5.7,1.8) 31(5.7,2.7) 32(5.7,3.6) 33(5.7,4.5)
  rect 0.5x1.2 smd: 12(-4.5,-5.7) 13(-3.6,-5.7) 14(-2.7,-5.7) 15(-1.8,-5.7) 16(-0.9,-5.7) 17(0,-5.7) 18(0.9,-5.7) 19(1.8,-5.7) 20(2.7,-5.7) 21(3.6,-5.7) 22(4.5,-5.7) 34(4.5,5.7) 35(3.6,5.7) 36(2.7,5.7) 37(1.8,5.7) 38(0.9,5.7) 39(0,5.7) 40(-0.9,5.7) 41(-1.8,5.7) 42(-2.7,5.7) 43(-3.6,5.7) 44(-4.5,5.7)
  round 0.6 smd: 45(-2.7,3.6) 46(-0.9,3.6) 47(0.9,3.6)
  silkscreen extent -7.17,-6 6,6, body extent -6.35,-6 6.35,6, height 3.81
INFORMATION [mil] "INFORMATION"
  rect 75x15 smd: 1(-82.68,38.39) 2(-82.68,12.8) 3(-82.68,-12.8) 4(-82.68,-38.39) 5(82.68,-38.39) 6(82.68,-12.8) 7(82.68,12.8) 8(82.68,38.39)
  silkscreen extent -59,-59 59,59, body extent -134,-75 134,75, height 150
PLACE_BOUND_BOTTOM [mm] "PLACE_BOUND_BOTTOM"
  round 1 smd: 1(0,0)
  TOP keep-out region: 1.261,0 1.218,-0.326 1.092,-0.63 0.892,-0.892 0.63,-1.092 0.326,-1.218 0,-1.261 -0.326,-1.218 -0.63,-1.092 -0.63,-1.092 -0.892,-0.892 -1.092,-0.63 -1.218,-0.326 -1.261,0 -1.218,0.326 -1.092,0.63 -0.892,0.892 -0.63,1.092 -0.63,1.092 -0.326,1.218 0,1.261 0.326,1.218 0.63,1.092 0.892,0.892 1.092,0.63 1.218,0.326 1.261,0
  TOP keep-out region: 1.261,0 1.218,-0.326 1.092,-0.63 0.892,-0.892 0.63,-1.092 0.326,-1.218 0,-1.261 -0.326,-1.218 -0.63,-1.092 -0.63,-1.092 -0.892,-0.892 -1.092,-0.63 -1.218,-0.326 -1.261,0 -1.218,0.326 -1.092,0.63 -0.892,0.892 -0.63,1.092 -0.63,1.092 -0.326,1.218 0,1.261 0.326,1.218 0.63,1.092 0.892,0.892 1.092,0.63 1.218,0.326 1.261,0
  body extent -1.26,-1.26 1.26,1.26, height 3.81
PLACE_BOUND_TOP [mm] "PLACE_BOUND_TOP"
  round 1 smd: 1(0,0)
  TOP keep-out region: 1.261,0 1.218,0.326 1.092,0.63 0.892,0.892 0.63,1.092 0.326,1.218 0,1.261 -0.326,1.218 -0.63,1.092 -0.63,1.092 -0.892,0.892 -1.092,0.63 -1.218,0.326 -1.261,0 -1.218,-0.326 -1.092,-0.63 -0.892,-0.892 -0.63,-1.092 -0.63,-1.092 -0.326,-1.218 0,-1.261 0.326,-1.218 0.63,-1.092 0.892,-0.892 1.092,-0.63 1.218,-0.326 1.261,0
  TOP keep-out region: 1.261,0 1.218,0.326 1.092,0.63 0.892,0.892 0.63,1.092 0.326,1.218 0,1.261 -0.326,1.218 -0.63,1.092 -0.63,1.092 -0.892,0.892 -1.092,0.63 -1.218,0.326 -1.261,0 -1.218,-0.326 -1.092,-0.63 -0.892,-0.892 -0.63,-1.092 -0.63,-1.092 -0.326,-1.218 0,-1.261 0.326,-1.218 0.63,-1.092 0.892,-0.892 1.092,-0.63 1.218,-0.326 1.261,0
  body extent -1.26,-1.26 1.26,1.26, height 3.81
SILKSCREEN_BOTTOM#1 [mm] "SILKSCREEN_BOTTOM"
  rect 0.8x0.9 smd: 1(0.7,0) 2(-0.7,0)
  silkscreen extent -1.35,-0.6 1.35,0.6, body extent -1.35,-0.6 1.35,0.6, height 3.81
SILKSCREEN_BOTTOM#2 [mm] "SILKSCREEN_BOTTOM"
  rect 0.55x0.55 smd: 1(-0.45,0) 2(0.45,0)
  TOP keep-out region: -0.127,-0.381 -0.127,0.381 0.127,0.381 0.127,-0.381
  silkscreen extent -0.9,-0.4 0.9,0.4, body extent -0.9,-0.4 0.9,0.4, height 3.81
SILKSCREEN_BOTTOM#3 [mm] "SILKSCREEN_BOTTOM"
  rect 0.55x0.55 smd: 1(0.45,0) 2(-0.45,0)
  TOP keep-out region: 0.127,0.381 0.127,-0.381 -0.127,-0.381 -0.127,0.381 0.127,0.381
  silkscreen extent -0.9,-0.4 0.9,0.4, body extent -0.9,-0.4 0.9,0.4, height 3.81
SILKSCREEN_BOTTOM#4 [mm] "SILKSCREEN_BOTTOM"
  rect 0.95x1.3 smd: 1(0.825,0) 2(-0.825,0)
  silkscreen extent -1.7,-0.95 1.7,0.95, body extent -1.7,-0.95 1.7,0.95, height 3.81
SILKSCREEN_BOTTOM#5 [mm] "SILKSCREEN_BOTTOM"
  rect 0.8x0.9 smd: 1(-0.7,0) 2(0.7,0)
  silkscreen extent -1.35,-0.6 1.35,0.6, body extent -1.35,-0.6 1.35,0.6, height 3.81
SILKSCREEN_BOTTOM#6 [mm] "SILKSCREEN_BOTTOM"
  rect 0.95x1.3 smd: 1(-0.825,0) 2(0.825,0)
  silkscreen extent -1.7,-0.95 1.7,0.95, body extent -1.7,-0.95 1.7,0.95, height 3.81
SILKSCREEN_BOTTOM#7 [mm] "SILKSCREEN_BOTTOM"
  rect 1.4x1.6 smd: 1(-1.168,0) 2(1.168,0)
  silkscreen extent -2.2,-1 2.2,1, body extent -2.2,-1 2.2,1, height 3.81
SILKSCREEN_BOTTOM#8 [mm] "SILKSCREEN_BOTTOM"
  rect 0.8x0.75 smd: A(1.7,0) C(-1.7,0)
  silkscreen extent -1.97,-0.8 1.35,1.02, body extent -2.2,-1 2.2,1, height 3.81
SILKSCREEN_BOTTOM#9 [mm] "SILKSCREEN_BOTTOM"
  rect 0.2x0.68 smd: 1(1,0.437) 2(0.5,0.437) 4(-0.5,0.437) 5(-1,0.437) 6(-1,-0.437) 7(-0.5,-0.437) 9(0.5,-0.437) 10(1,-0.437)
  rect 0.4x0.75 smd: 3(0,0.395) 8(0,-0.395)
  silkscreen extent -1.25,-1 1.94,0.5, body extent -1.39,-0.64 1.39,0.64, height 3.81
SILKSCREEN_BOTTOM#10 [mm] "SILKSCREEN_BOTTOM"
  rect 0.57x0.62 smd: 1(-0.48,0) 2(0.48,0)
  silkscreen extent -0.98,-0.52 1,0.52, body extent -0.92,-0.46 0.92,0.46, height 3.81
SILKSCREEN_BOTTOM#11 [mm] "SILKSCREEN_BOTTOM"
  rect 0.2x0.68 smd: 1(-1,-0.437) 2(-0.5,-0.437) 4(0.5,-0.437) 5(1,-0.437) 6(1,0.437) 7(0.5,0.437) 9(-0.5,0.437) 10(-1,0.437)
  rect 0.4x0.75 smd: 3(0,-0.395) 8(0,0.395)
  silkscreen extent -1.43,-0.5 1.25,1.69
SILKSCREEN_BOTTOM#12 [mm] "SILKSCREEN_BOTTOM"
  rect 1.6x0.3 smd: 1(-40.525,-9.25) 2(-34.075,-9) 3(-40.525,-8.75) 4(-34.075,-8.5) 5(-40.525,-8.25) 6(-34.075,-8) 7(-40.525,-7.75) 8(-34.075,-7.5) 9(-40.525,-7.25) 10(-34.075,-7) 11(-40.525,-6.75) 12(-34.075,-6.5) 13(-40.525,-6.25) 14(-34.075,-6) 15(-40.525,-5.75) 16(-34.075,-5.5) 17(-40.525,-5.25) 18(-34.075,-5) 19(-40.525,-4.75) 20(-34.075,-4.5) 21(-40.525,-4.25) 22(-34.075,-4) 23(-40.525,-3.75) 24(-34.075,-3.5) 25(-40.525,-3.25) 26(-34.075,-3) 27(-40.525,-2.75) 28(-34.075,-2.5) 29(-40.525,-2.25) 30(-34.075,-2) 31(-40.525,-1.75) 32(-34.075,-1.5) 33(-40.525,-1.25) 34(-34.075,-1) 35(-40.525,-0.75) 36(-34.075,-0.5) 37(-40.525,-0.25) 38(-34.075,0) 39(-40.525,0.25) 40(-34.075,0.5) 41(-40.525,0.75) 42(-34.075,1) 43(-40.525,1.25) 44(-34.075,1.5) 45(-40.525,1.75) 46(-34.075,2) 47(-40.525,2.25) 48(-34.075,2.5) 49(-40.525,2.75) 50(-34.075,3) 51(-40.525,3.25) 52(-34.075,3.5) 53(-40.525,3.75) 54(-34.075,4) 55(-40.525,4.25) 56(-34.075,4.5) 57(-40.525,4.75) 58(-34.075,5) 67(-40.525,7.25) 68(-34.075,7.5) 69(-40.525,7.75) 70(-34.075,8) 71(-40.525,8.25) 72(-34.075,8.5) 73(-40.525,8.75) 74(-34.075,9) 75(-40.525,9.25)
  round 1.6 / inner round 1.524 / far side round 1.6 hole 1.6 unplated: 76(-35.8,10)
  round 1.118 / inner round 1.524 / far side round 1.118 hole 1.118 unplated: 77(-35.8,-10)
  rect 2.8x1.2 smd: G1(-40.3,10.35) G2(-40.3,-10.35)
  round 4.5 / inner round 1.524 / far side round 5 hole 2.6: G3(42,0) G4(8.8,0)
  silkscreen extent -42,-11.2 42,11.2, body extent -42,-11.2 42,11.2, height 3.81
SILKSCREEN_BOTTOM#13 [mm] "SILKSCREEN_BOTTOM"
  rect 0.85x0.3 smd: 1(-0.8,0.5) 2(-0.8,-0.5) 3(0.8,0)
  silkscreen extent -1.07,-0.8 0,1.28, body extent -1.5,-1.1 1.5,1.1, height 3.81
SILKSCREEN_BOTTOM#14 [mm] "SILKSCREEN_BOTTOM"
  rect 1.05x0.65 smd: 1(1.15,-0.95) 2(1.15,0.95) 3(-1.15,0)
  silkscreen extent -0.3,-1.92 1.52,1.45, body extent -1.95,-1.75 1.95,1.75, height 3.81
SILKSCREEN_BOTTOM#15 [mm] "SILKSCREEN_BOTTOM"
  rect 1x1.2 smd: 1(-1,0) 2(1,0)
  TOP keep-out region: -0.381,0.635 -0.381,-0.635 0.381,-0.635 0.381,0.635 -0.381,0.635
  silkscreen extent -1.7,-0.95 1.7,0.95, body extent -1.78,-1.02 1.78,1.02, height 3.81
SILKSCREEN_BOTTOM#16 [mm] "SILKSCREEN_BOTTOM"
  rect 0.5x0.399 smd: 1(0.5,-0.8) 4(0.5,0.8) 5(-0.5,0.8) 8(-0.5,-0.8)
  rect 0.5x0.3 smd: 2(0.5,-0.25) 3(0.5,0.25) 6(-0.5,0.25) 7(-0.5,-0.25)
  silkscreen extent -0.98,-1.28 0.98,1.28, body extent -0.9,-1.2 0.9,1.2, height 3.81
SILKSCREEN_BOTTOM#17 [mm] "SILKSCREEN_BOTTOM"
  rect 0.5x0.399 smd: 1(-0.5,0.8) 4(-0.5,-0.8) 5(0.5,-0.8) 8(0.5,0.8)
  rect 0.5x0.3 smd: 2(-0.5,0.25) 3(-0.5,-0.25) 6(0.5,-0.25) 7(0.5,0.25)
  silkscreen extent -0.98,-1.28 0.98,1.28, body extent -0.9,-1.2 0.9,1.2, height 3.81
SILKSCREEN_BOTTOM#18 [mm] "SILKSCREEN_BOTTOM"
  rect 1.829x1.397 smd: C1(13.199,2.119) C2(13.199,-0.421) C3(13.199,-2.961) C5(-9.772,2.119) C6(-9.772,-0.421) C7(-9.772,-2.961) CD1(13.199,-10.251) CD2(-9.772,-10.251)
  silkscreen extent -16.98,-12.51 17.02,12.49, body extent -17.05,-12.5 17.05,12.5, height 3.81
SILKSCREEN_BOTTOM#19 [mm] "SILKSCREEN_BOTTOM"
  rect 0.9x1.2 smd: 1(2.339,-0.749) 2(-2.263,-0.749)
  rect 1.15x1.3 smd: 3(1.713,0.801) 4(-1.637,0.801)
  round 0.6 / inner round 1.524 / far side round 0.6 hole 0.6 unplated: ""(-0.813,-0.749) ""(0.889,-0.749)
  silkscreen extent -2.86,-2.65 2.94,1.55, body extent -2.86,-1.44 2.86,1.44, height 3.81
SILKSCREEN_BOTTOM#20 [mm] "SILKSCREEN_BOTTOM"
  rect 1.1x0.6 smd: 1(-1.35,0.95) 2(-1.35,0) 3(-1.35,-0.95) 4(1.35,-0.95) 5(1.35,0.95)
  silkscreen extent -1.77,-1.45 0.48,1.87, body extent -2.15,-1.8 2.15,1.8, height 3.81
SILKSCREEN_BOTTOM#21 [mm] "SILKSCREEN_BOTTOM"
  rect 1.1x0.6 smd: 1(1.35,-0.95) 2(1.35,0) 3(1.35,0.95) 4(-1.35,0.95) 5(-1.35,-0.95)
  silkscreen extent -0.48,-1.65 1.78,1.45, body extent -2.15,-1.8 2.15,1.8, height 3.81
SILKSCREEN_TOP#1 [mm] "SILKSCREEN_TOP"
  rect 0.55x0.55 smd: 1(-0.45,0) 2(0.45,0)
  TOP keep-out region: -0.127,-0.381 0.127,-0.381 0.127,0.381 -0.127,0.381
  silkscreen extent -0.9,-0.4 0.9,0.4, body extent -0.9,-0.4 0.9,0.4, height 3.81
SILKSCREEN_TOP#2 [mm] "SILKSCREEN_TOP"
  rect 0.95x1.3 smd: 1(-0.825,0) 2(0.825,0)
  silkscreen extent -1.7,-0.95 1.7,0.95, body extent -1.7,-0.95 1.7,0.95, height 3.81
SILKSCREEN_TOP#3 [mm] "SILKSCREEN_TOP"
  rect 3.15x1.6 smd: 1(-2.45,0) 2(2.45,0)
  silkscreen extent -3.92,-3.3 3.3,3.3, body extent -4.55,-3.9 4.55,3.9, height 3.81
SILKSCREEN_TOP#4 [mm] "SILKSCREEN_TOP"
  rect 0.8x0.9 smd: 1(-0.7,0) 2(0.7,0)
  silkscreen extent -1.35,-0.6 1.35,0.6, body extent -1.35,-0.6 1.35,0.6, height 3.81
SILKSCREEN_TOP#5 [mm] "SILKSCREEN_TOP"
  rect 1.85x1.45 smd: A(1.95,0) C(-1.95,0)
  silkscreen extent -3.52,-1.35 2.5,1.35, body extent -3,-1.55 3,1.55, height 3.81
SILKSCREEN_TOP#6 [mm] "SILKSCREEN_TOP"
  rect 0.57x0.62 smd: 1(-0.48,0) 2(0.48,0)
  silkscreen extent -0.98,-0.52 1,0.52, body extent -0.92,-0.46 0.92,0.46, height 3.81
SILKSCREEN_TOP#7 [mm] "SILKSCREEN_TOP"
  rect 0.2x0.68 smd: 1(-1,-0.437) 2(-0.5,-0.437) 4(0.5,-0.437) 5(1,-0.437) 6(1,0.437) 7(0.5,0.437) 9(-0.5,0.437) 10(-1,0.437)
  rect 0.4x0.75 smd: 3(0,-0.395) 8(0,0.395)
  silkscreen extent -1.43,-0.5 1.25,1.69
SILKSCREEN_TOP#8 [mm] "SILKSCREEN_TOP"
  rect 1.43x1.53 smd: A(-1.84,0) C(1.84,0)
  silkscreen extent -1.75,-1.3 2.42,1.39, body extent -2.66,-1.45 2.66,1.45, height 3.81
SILKSCREEN_TOP#9 [mm] "SILKSCREEN_TOP"
  rect 0.94x0.95 smd: A(-1.45,0) C(1.45,0)
  silkscreen extent -0.6,-0.8 2.48,0.8, body extent -2.02,-0.95 2.02,0.95, height 3.81
SILKSCREEN_TOP#10 [mm] "SILKSCREEN_TOP"
  rect 0.9x0.5 smd: A(1.3,0) C(-1.3,0)
  silkscreen extent -1.62,-0.65 0.85,0.87, body extent -2,-0.95 2,0.95, height 3.81
SILKSCREEN_TOP#11 [mm] "SILKSCREEN_TOP"
  rect 0.65x0.5 smd: A(0.9,0) C(-0.9,0)
  silkscreen extent -1.22,-0.58 0.6,0.87, body extent -1.5,-0.7 1.5,0.7, height 3.81
SILKSCREEN_TOP#12 [mm] "SILKSCREEN_TOP"
  rect 1.05x0.6 smd: 1(-1.35,0.95) 2(-1.35,0) 3(-1.35,-0.95) 4(1.35,-0.95) 5(1.35,0) 6(1.35,0.95)
  silkscreen extent -1.72,-1.5 0.5,1.87, body extent -2.15,-1.8 2.15,1.8, height 3.81
SILKSCREEN_TOP#13 [mm] "SILKSCREEN_TOP"
  round 4.5 / inner round 1.524 / far side round 2.7 hole 1.7: 1(0,0)
  body extent -2.31,-2.31 2.31,2.31, height 3.81
SILKSCREEN_TOP#14 [mm] "SILKSCREEN_TOP"
  round 2.3 / inner round 1.524 / far side round 2.3 hole 2.3 unplated: 1(-1.7,-1.301)
  rect 3x1.6 / inner round 1.524 / far side rect 3x1.6 hole 0.8: 2(4.4,3.899) 3(4.4,-1.301) 4(4.4,-4.702)
  rect 2.5x1 / inner round 1.524 / far side rect 2.5x1 hole 0.6: 5(-2.8,4.849) 6(-2.8,-4.951)
  silkscreen extent -8.8,-5.1 5.8,5.1, body extent -5.8,-5.1 5.8,5.1, height 3.81
SILKSCREEN_TOP#15 [mm] "SILKSCREEN_TOP"
  rect 0.25x1.75 smd: 1(-33.488,-24.041) 2(-33.238,-15.841) 3(-32.988,-24.041) 4(-32.738,-15.841) 5(-32.488,-24.041) 6(-32.238,-15.841) 7(-31.988,-24.041) 8(-31.738,-15.841) 9(-31.488,-24.041) 10(-31.238,-15.841) 11(-30.988,-24.041) 12(-30.738,-15.841) 13(-30.488,-24.041) 14(-30.238,-15.841) 15(-29.988,-24.041) 16(-29.738,-15.841) 17(-29.488,-24.041) 18(-29.238,-15.841) 19(-28.988,-24.041) 20(-28.738,-15.841) 21(-28.488,-24.041) 22(-28.238,-15.841) 23(-27.988,-24.041) 24(-27.738,-15.841) 25(-27.488,-24.041) 26(-27.238,-15.841) 27(-26.988,-24.041) 28(-26.738,-15.841) 29(-26.488,-24.041) 30(-26.238,-15.841) 31(-25.988,-24.041) 32(-25.738,-15.841) 33(-25.488,-24.041) 34(-25.238,-15.841) 35(-24.988,-24.041) 36(-24.738,-15.841) 37(-24.488,-24.041) 38(-24.238,-15.841) 39(-23.988,-24.041) 40(-23.738,-15.841) 41(-23.488,-24.041) 42(-23.238,-15.841) 43(-22.988,-24.041) 44(-22.738,-15.841) 45(-22.488,-24.041) 46(-22.238,-15.841) 47(-21.988,-24.041) 48(-21.738,-15.841) 49(-21.488,-24.041) 50(-21.238,-15.841) 51(-20.988,-24.041) 52(-20.738,-15.841) 53(-20.488,-24.041) 54(-20.238,-15.841) 55(-19.988,-24.041) 56(-19.738,-15.841) 57(-19.488,-24.041) 58(-19.238,-15.841) 59(-18.988,-24.041) 60(-18.738,-15.841) 61(-18.488,-24.041) 62(-18.238,-15.841) 63(-17.988,-24.041) 64(-17.738,-15.841) 65(-17.488,-24.041) 66(-17.238,-15.841) 67(-16.988,-24.041) 68(-16.738,-15.841) 69(-16.488,-24.041) 70(-16.238,-15.841) 71(-15.988,-24.041) 72(-15.738,-15.841) 73(-15.488,-24.041) 74(-15.238,-15.841) 75(-14.988,-24.041) 76(-14.738,-15.841) 77(-14.488,-24.041) 78(-14.238,-15.841) 79(-13.988,-24.041) 80(-13.738,-15.841) 81(-13.488,-24.041) 82(-13.238,-15.841) 83(-12.988,-24.041) 84(-12.738,-15.841) 85(-12.488,-24.041) 86(-12.238,-15.841) 87(-11.988,-24.041) 88(-11.738,-15.841) 89(-11.488,-24.041) 90(-11.238,-15.841) 91(-10.988,-24.041) 92(-10.738,-15.841) 93(-10.488,-24.041) 94(-10.238,-15.841) 95(-9.988,-24.041) 96(-9.738,-15.841) 97(-9.488,-24.041) 98(-9.238,-15.841) 99(-8.988,-24.041) 100(-8.738,-15.841) 101(-8.488,-24.041) 102(-8.238,-15.841) 103(-7.988,-24.041) 104(-7.738,-15.841) 105(-7.488,-24.041) 106(-7.238,-15.841) 107(-6.988,-24.041) 108(-6.738,-15.841) 109(-6.488,-24.041) 110(-6.238,-15.841) 111(-5.988,-24.041) 112(-5.738,-15.841) 113(-5.488,-24.041) 114(-5.238,-15.841) 115(-4.988,-24.041) 116(-4.738,-15.841) 117(-4.488,-24.041) 118(-4.238,-15.841) 119(-3.988,-24.041) 120(-3.738,-15.841) 121(-3.488,-24.041) 122(-3.238,-15.841) 123(-2.988,-24.041) 124(-2.738,-15.841) 125(-2.488,-24.041) 126(-2.238,-15.841) 127(-1.988,-24.041) 128(-1.738,-15.841) 129(-1.488,-24.041) 130(-1.238,-15.841) 131(-0.988,-24.041) 132(-0.738,-15.841) 133(-0.488,-24.041) 134(-0.238,-15.841) 135(0.012,-24.041) 136(0.262,-15.841) 137(0.512,-24.041) 138(0.762,-15.841) 139(1.012,-24.041) 140(1.262,-15.841) 141(1.512,-24.041) 142(1.762,-15.841) 143(2.012,-24.041) 144(2.262,-15.841) 145(4.512,-24.041) 146(4.762,-15.841) 147(5.012,-24.041) 148(5.262,-15.841) 149(5.512,-24.041) 150(5.762,-15.841) 151(6.012,-24.041) 152(6.262,-15.841) 153(6.512,-24.041) 154(6.762,-15.841) 155(7.012,-24.041) 156(7.262,-15.841) 157(7.512,-24.041) 158(7.762,-15.841) 159(8.012,-24.041) 160(8.262,-15.841) 161(8.512,-24.041) 162(8.762,-15.841) 163(9.012,-24.041) 164(9.262,-15.841) 165(9.512,-24.041) 166(9.762,-15.841) 167(10.012,-24.041) 168(10.262,-15.841) 169(10.512,-24.041) 170(10.762,-15.841) 171(11.012,-24.041) 172(11.262,-15.841) 173(11.512,-24.041) 174(11.762,-15.841) 175(12.012,-24.041) 176(12.262,-15.841) 177(12.512,-24.041) 178(12.762,-15.841) 179(13.012,-24.041) 180(13.262,-15.841) 181(13.512,-24.041) 182(13.762,-15.841) 183(14.012,-24.041) 184(14.262,-15.841) 185(14.512,-24.041) 186(14.762,-15.841) 187(15.012,-24.041) 188(15.262,-15.841) 189(15.512,-24.041) 190(15.762,-15.841) 191(16.012,-24.041) 192(16.262,-15.841) 193(16.512,-24.041) 194(16.762,-15.841) 195(17.012,-24.041) 196(17.262,-15.841) 197(17.512,-24.041) 198(17.762,-15.841) 199(18.012,-24.041) 200(18.262,-15.841) 201(18.512,-24.041) 202(18.762,-15.841) 203(19.012,-24.041) 204(19.262,-15.841) 205(19.512,-24.041) 206(19.762,-15.841) 207(20.012,-24.041) 208(20.262,-15.841) 209(20.512,-24.041) 210(20.762,-15.841) 211(21.012,-24.041) 212(21.262,-15.841) 213(21.512,-24.041) 214(21.762,-15.841) 215(22.012,-24.041) 216(22.262,-15.841) 217(22.512,-24.041) 218(22.762,-15.841) 219(23.012,-24.041) 220(23.262,-15.841) 221(23.512,-24.041) 222(23.762,-15.841) 223(24.012,-24.041) 224(24.262,-15.841) 225(24.512,-24.041) 226(24.762,-15.841) 227(25.012,-24.041) 228(25.262,-15.841) 229(25.512,-24.041) 230(25.762,-15.841) 231(26.012,-24.041) 232(26.262,-15.841) 233(26.512,-24.041) 234(26.762,-15.841) 235(27.012,-24.041) 236(27.262,-15.841) 237(27.512,-24.041) 238(27.762,-15.841) 239(28.012,-24.041) 240(28.262,-15.841) 241(28.512,-24.041) 242(28.762,-15.841) 243(29.012,-24.041) 244(29.262,-15.841) 245(29.512,-24.041) 246(29.762,-15.841) 247(30.012,-24.041) 248(30.262,-15.841) 249(30.512,-24.041) 250(30.762,-15.841) 251(31.012,-24.041) 252(31.262,-15.841) 253(31.512,-24.041) 254(31.762,-15.841) 255(32.012,-24.041) 256(32.262,-15.841) 257(32.512,-24.041) 258(32.762,-15.841) 259(33.012,-24.041) 260(33.262,-15.841)
  rect 3.505x4.597 smd: N1(-33.913,-7.941) N2(33.687,-7.941)
  round 5 / inner round 1.524 / far side round 3.2 hole 2.2: N3(-32.513,22.359) N4(32.287,22.359)
  round 1.6 / inner round 1.524 / far side round 1.6 hole 1.6 unplated: ""(-34.513,-19.941)
  round 1.1 / inner round 1.524 / far side round 1.1 hole 1.1 unplated: ""(34.287,-19.941)
  Multi-Layer keep-out region: -35.698,-19.941 -35.657,-20.247 -35.539,-20.533 -35.351,-20.779 -35.105,-20.967 -34.819,-21.085 -34.513,-21.126 -34.206,-21.085 -33.92,-20.967 -33.92,-20.967 -33.675,-20.779 -33.486,-20.533 -33.368,-20.247 -33.328,-19.941 -33.368,-19.634 -33.486,-19.348 -33.675,-19.103 -33.92,-18.914 -33.92,-18.914 -34.206,-18.796 -34.513,-18.756 -34.819,-18.796 -35.105,-18.914 -35.351,-19.103 -35.539,-19.348 -35.657,-19.634 -35.698,-19.941
  Multi-Layer keep-out region: 33.354,-19.941 33.386,-20.182 33.479,-20.407 33.628,-20.6 33.821,-20.749 34.046,-20.842 34.287,-20.874 34.529,-20.842 34.754,-20.749 34.754,-20.749 34.947,-20.6 35.095,-20.407 35.188,-20.182 35.22,-19.941 35.188,-19.699 35.095,-19.474 34.947,-19.281 34.754,-19.133 34.754,-19.133 34.529,-19.04 34.287,-19.008 34.046,-19.04 33.821,-19.133 33.628,-19.281 33.479,-19.474 33.386,-19.699 33.354,-19.941
  silkscreen extent -38.99,-26 39.01,25.06, body extent -38.97,-25.06 38.97,25.06, height 3.81
SILKSCREEN_TOP#16 [mm] "SILKSCREEN_TOP"
  oval 0.7x2.3 smd: 1(2.285,6.625) 2(1.185,6.625) 3(0.085,6.625) 4(-1.015,6.625) 5(-2.115,6.625) 6(-3.215,6.625) 7(-4.315,6.625) 8(-5.415,6.625) 9(-6.515,6.625)
  rect 1.2x1.4 smd: 10(-7.715,5.925)
  rect 1.6x1.4 smd: 11(6.885,5.925)
  rect 1.2x2.2 smd: 12(-7.715,-3.775) 13(7.785,-3.775)
  round 1 / inner round 1.524 / far side round 1 hole 1: ""(-4.915,-4.075) ""(3.085,-4.075)
  silkscreen extent -7.72,-7.87 7.79,6.62, body extent -8.44,-7.97 8.44,7.97, height 3.81
SILKSCREEN_TOP#17 [mm] "SILKSCREEN_TOP"
  rect 0.635x1.6 smd: 1(-1.25,1.8) 2(0,1.8) 3(1.25,1.8)
  rect 2.134x3.048 smd: 4(-3.8,-1.1) 5(3.8,-1.1)
  silkscreen extent -4.3,-2.7 4.3,1, body extent -4.3,-2.7 4.3,2.7, height 3.81
SILKSCREEN_TOP#18 [mm] "SILKSCREEN_TOP"
  rect 0.3x1.25 smd: A1(-3.287,3.607) A4(-2.536,3.607) A5(-1.187,3.607) A6(-0.187,3.607) A7(0.314,3.607) A8(-1.687,3.607) A9(2.614,3.607) A12(3.414,3.607) B1(3.114,3.607) B4(2.314,3.607) B5(1.814,3.607) B6(0.814,3.607) B7(-0.687,3.607) B8(1.314,3.607) B9(-2.236,3.607) B12(-2.987,3.607)
  oval 1.2x2.5 / inner round 1.524 / far side oval 1.2x2.5 hole 1.8 slot 0.6 at 0 deg: H1(-4.257,3.007) H2(4.384,3.007)
  oval 1x2 / inner round 1.524 / far side oval 1x2 hole 1.5 slot 0.6 at 0 deg: H3(-4.257,-1.143) H4(4.384,-1.143)
  round 0.711 / inner round 1.524 / far side round 0.711 hole 0.711 unplated: NC1(-2.827,2.507) NC2(2.954,2.507)
  silkscreen extent -4.44,-3.74 4.56,3.61, body extent -4.51,-3.68 4.51,3.68, height 3.81
SILKSCREEN_TOP#19 [mm] "SILKSCREEN_TOP"
  round 1.118 / inner round 1.524 / far side round 1.118 hole 0.711: 1(-3.5,2.65) 2(-1,2.65) 3(1,2.65) 4(3.5,2.65) 5(4,4.15) 6(2,4.15) 7(0,4.15) 8(-2,4.15) 9(-4,4.15) 10(-3.5,5.85) 11(-1,5.85) 12(1,5.85) 13(3.5,5.85) 14(4,7.35) 15(2,7.35) 16(0,7.35) 17(-2,7.35) 18(-4,7.35)
  round 2.794 / inner round 1.524 / far side round 2.794 hole 2.362: 19(-6.57,6.33) 20(6.57,6.33) 21(6.57,0.65) 22(-6.57,0.65)
  silkscreen extent -7.3,-8.95 7.3,8.95, body extent -7.4,-9.05 7.4,9.05, height 3.81
SILKSCREEN_TOP#20 [mm] "SILKSCREEN_TOP"
  rect 0.635x1.6 smd: 1(-0.625,1.8) 2(0.625,1.8)
  rect 2.134x3.048 smd: 3(-3.175,-1.1) 4(3.175,-1.1)
  silkscreen extent -3.7,-2.7 3.7,1, body extent -3.7,-2.7 3.7,2.7, height 3.81
SILKSCREEN_TOP#21 [mm] "SILKSCREEN_TOP"
  rect 0.508x2.032 smd: 1(11.75,26.9) 2(11.349,18.701) 3(10.95,26.9) 4(10.549,18.701) 5(10.15,26.9) 6(9.748,18.701) 7(9.35,26.9) 8(8.948,18.701) 9(8.55,26.9) 10(8.148,18.701) 11(7.749,26.9) 12(7.348,18.701) 13(6.949,26.9) 14(6.548,18.701) 15(6.149,26.9) 16(5.751,18.701) 17(2.149,26.9) 18(1.75,18.701) 19(1.349,26.9) 20(0.95,18.701) 21(0.549,26.9) 22(0.15,18.701) 23(-0.252,26.9) 24(-0.65,18.701) 25(-1.052,26.9) 26(-1.45,18.701) 27(-1.852,26.9) 28(-2.25,18.701) 29(-2.652,26.9) 30(-3.05,18.701) 31(-3.452,26.9) 32(-3.851,18.701) 33(-4.252,26.9) 34(-4.651,18.701) 35(-5.049,26.9) 36(-5.451,18.701) 37(-5.852,26.9) 38(-6.251,18.701) 39(-6.65,26.9) 40(-7.051,18.701) 41(-7.45,26.9) 42(-7.851,18.701) 43(-8.25,26.9) 44(-8.651,18.701) 45(-9.05,26.9) 46(-9.451,18.701) 47(-9.85,26.9) 48(-10.251,18.701) 49(-10.65,26.9) 50(-11.051,18.701) 51(-11.45,26.9) 52(-11.852,18.701)
  round 1.651 / inner round 1.524 / far side round 1.651 hole 1.651 unplated: 53(12.448,22.8)
  round 1.143 / inner round 1.524 / far side round 1.143 hole 1.143 unplated: 54(-12.55,22.8)
  rect 2.413x3.302 smd: 55(-14.701,26.3) 56(14.6,26.3)
  Multi-Layer keep-out region: 13.665,22.8 13.624,23.115 13.502,23.408 13.309,23.66 13.057,23.854 12.764,23.975 12.449,24.016 12.135,23.975 11.841,23.854 11.841,23.854 11.589,23.66 11.396,23.408 11.275,23.115 11.233,22.8 11.275,22.486 11.396,22.192 11.589,21.94 11.841,21.747 11.841,21.747 12.135,21.626 12.449,21.584 12.764,21.626 13.057,21.747 13.309,21.94 13.502,22.192 13.624,22.486 13.665,22.8
  Multi-Layer keep-out region: -11.589,22.8 -11.622,23.049 -11.718,23.281 -11.871,23.48 -12.07,23.633 -12.302,23.729 -12.551,23.762 -12.8,23.729 -13.032,23.633 -13.032,23.633 -13.231,23.48 -13.384,23.281 -13.48,23.049 -13.512,22.8 -13.48,22.551 -13.384,22.32 -13.231,22.12 -13.032,21.968 -13.032,21.968 -12.8,21.872 -12.551,21.839 -12.302,21.872 -12.07,21.968 -11.871,22.12 -11.718,22.32 -11.622,22.551 -11.589,22.8
  silkscreen extent -15.05,-28.15 14.95,26.03, body extent -16.05,-28.2 16.05,28.2, height 3.81
SILKSCREEN_TOP#22 [mm] "SILKSCREEN_TOP"
  rect 0.7x0.45 smd: 1(-0.85,0.4) 2(-0.85,-0.4) 3(0.85,-0.4) 4(0.85,0.4)
  silkscreen extent -1,-0.6 1,0.6, body extent -1.35,-0.85 1.35,0.85, height 3.81
SILKSCREEN_TOP#23 [mm] "SILKSCREEN_TOP"
  rect 0.75x0.9 smd: 1(-0.7,0) 2(0.7,0)
  silkscreen extent -1.2,-0.6 1.2,0.6, body extent -1.2,-0.6 1.2,0.6, height 3.81
SILKSCREEN_TOP#24 [mm] "SILKSCREEN_TOP"
  rect 0.85x0.3 smd: 1(-0.8,0.5) 2(-0.8,-0.5) 3(0.8,0)
  silkscreen extent -1.07,-0.8 0,1.27, body extent -1.5,-1.1 1.5,1.1, height 3.81
SILKSCREEN_TOP#25 [mm] "SILKSCREEN_TOP"
  rect 1.05x0.65 smd: 1(-1.15,0.95) 2(-1.15,-0.95) 3(1.15,0)
  silkscreen extent -1.52,-1.45 0.3,1.92, body extent -1.95,-1.75 1.95,1.75, height 3.81
SILKSCREEN_TOP#26 [mm] "SILKSCREEN_TOP"
  rect 1x1.2 smd: 1(-1,0) 2(1,0)
  TOP keep-out region: -0.381,0.635 -0.381,-0.635 0.381,-0.635 0.381,0.635 -0.381,0.635
  silkscreen extent -1.7,-0.95 1.7,0.95, body extent -1.78,-1.02 1.78,1.02, height 3.81
SILKSCREEN_TOP#27 [mm] "SILKSCREEN_TOP"
  rect 0.65x0.8 smd: 1(-0.725,0) 2(0.725,0)
  TOP keep-out region: -0.254,0.381 -0.254,-0.381 0.254,-0.381 0.254,0.381 -0.254,0.381
  silkscreen extent -1.35,-0.6 1.35,0.6, body extent -1.4,-0.64 1.4,0.64, height 3.81
SILKSCREEN_TOP#28 [mm] "SILKSCREEN_TOP"
  rect 0.5x0.399 smd: 1(-0.5,0.8) 4(-0.5,-0.8) 5(0.5,-0.8) 8(0.5,0.8)
  rect 0.5x0.3 smd: 2(-0.5,0.25) 3(-0.5,-0.25) 6(0.5,-0.25) 7(0.5,0.25)
  silkscreen extent -0.98,-1.28 0.98,1.28, body extent -0.9,-1.2 0.9,1.2, height 3.81
SILKSCREEN_TOP#29 [mm] "SILKSCREEN_TOP"
  rect 0.47x0.26 smd: 1(-0.74,0.5) 2(-0.74,0) 3(-0.74,-0.5) 4(0.74,-0.5) 5(0.74,0) 6(0.74,0.5)
  silkscreen extent -1.38,-0.8 0,0.9, body extent -1.08,-0.95 1.08,0.95, height 3.81
SILKSCREEN_TOP#30 [mm] "SILKSCREEN_TOP"
  rect 1.1x0.6 smd: 1(-1.35,0.95) 2(-1.35,0) 3(-1.35,-0.95) 4(1.35,-0.95) 5(1.35,0.95)
  silkscreen extent -1.78,-1.45 0.48,1.87, body extent -2.15,-1.8 2.15,1.8, height 3.81
SILKSCREEN_TOP#31 [mm] "SILKSCREEN_TOP"
  rect 0.95x0.4 smd: 1(-1.1,0.65) 2(-1.1,0) 3(-1.1,-0.65) 4(1.1,-0.65) 5(1.1,0.65)
  silkscreen extent -1.42,-1 0.3,1.47, body extent -1.85,-1.35 1.85,1.35, height 3.81
SILKSCREEN_TOP#32 [mm] "SILKSCREEN_TOP"
  rect 0.7x0.2 smd: 1(-2.35,1.8) 2(-2.35,1.4) 3(-2.35,1) 4(-2.35,0.6) 5(-2.35,0.2) 6(-2.35,-0.2) 7(-2.35,-0.6) 8(-2.35,-1) 9(-2.35,-1.4) 10(-2.35,-1.8) 21(2.35,-1.8) 22(2.35,-1.4) 23(2.35,-1) 24(2.35,-0.6) 25(2.35,-0.2) 26(2.35,0.2) 27(2.35,0.6) 28(2.35,1) 29(2.35,1.4) 30(2.35,1.8)
  rect 0.2x0.7 smd: 11(-1.8,-2.35) 12(-1.4,-2.35) 13(-1,-2.35) 14(-0.6,-2.35) 15(-0.2,-2.35) 16(0.2,-2.35) 17(0.6,-2.35) 18(1,-2.35) 19(1.4,-2.35) 20(1.8,-2.35) 31(1.8,2.35) 32(1.4,2.35) 33(1,2.35) 34(0.6,2.35) 35(0.2,2.35) 36(-0.2,2.35) 37(-0.6,2.35) 38(-1,2.35) 39(-1.4,2.35) 40(-1.8,2.35)
  rect 3.2x3.2 smd: 41(0,0)
  silkscreen extent -3.1,-2.5 2.5,2.5, body extent -2.6,-2.6 2.6,2.6, height 3.81
SILKSCREEN_TOP#33 [mm] "SILKSCREEN_TOP"
  rect 1.2x1.3 smd: 1(-0.9,1.2) 2(-0.9,-1.2) 3(0.9,-1.2) 4(0.9,1.2)
  silkscreen extent -2.12,-1.6 1.3,1.6, body extent -1.6,-1.95 1.6,1.95, height 3.81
